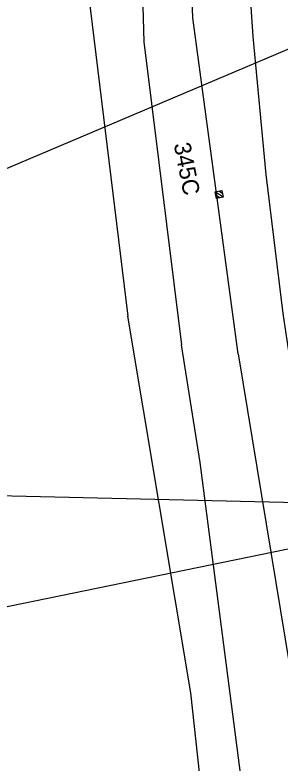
# Model space of a CAD drawing. Extents: x -545846 to -545044, y -1122650 to -1119108.
# Drawn here: x -545674.1 to -545654.2, y -1119663 to -1119607 of the extents above; entities that cross this region are included whole.
import ezdxf

# ---------------------------------------------------------------- set-up
doc = ezdxf.new("R2010")
doc.units = 0
for name, color, linetype in [('Vrstva 1 - Koleje', 7, 'Continuous'), ('Vrstva 11', 7, 'Continuous'), ('Vrstva 49', 7, 'Continuous'), ('Vrstva 62', 7, 'Continuous'), ('Vrstva 63', 7, 'Continuous')]:
    doc.layers.add(name, color=color, linetype=linetype)

msp = doc.modelspace()

# ---------------------------------------------------------------- linework, layer by layer
at = {"layer": 'Vrstva 1 - Koleje'}
msp.add_lwpolyline([(-545673.811, -1119482.836), (-545671.313, -1119495.675), (-545669.505, -1119504.975), (-545667.947, -1119513.018), (-545662.4, -1119541.424), (-545660.697, -1119551.332), (-545659.275, -1119561.505), (-545658.148, -1119572.104), (-545657.527, -1119582.463), (-545657.339, -1119589.06), (-545656.945, -1119598.604), (-545656.274, -1119608.583), (-545655.31, -1119618.93), (-545654.021, -1119629.341), (-545652.534, -1119639.322), (-545651.124, -1119648.586), (-545649.453, -1119659.616), (-545647.771, -1119670.646), (-545646.146, -1119681.578), (-545645.086, -1119692.159), (-545644.623, -1119702.795), (-545644.886, -1119713.798)], dxfattribs=at)
at = {"layer": 'Vrstva 11'}
for p, q in [((-545658.503, -1119620.61), (-545659.088, -1119620.216)), ((-545658.552, -1119620.351), (-545658.83, -1119620.164)), ((-545658.763, -1119620.661), (-545659.037, -1119620.476))]:
    msp.add_line(p, q, dxfattribs=at)
msp.add_lwpolyline([(-545658.992, -1119620.705), (-545659.088, -1119620.215), (-545658.598, -1119620.119), (-545658.502, -1119620.609)], close=True, dxfattribs=at)
msp.add_lwpolyline([(-545658.992, -1119620.705), (-545659.088, -1119620.215), (-545658.598, -1119620.119), (-545658.502, -1119620.609), (-545658.992, -1119620.705)], dxfattribs=at)
at = {"layer": 'Vrstva 49'}
for points in [[(-545657.384, -1119632.351), (-545660.766, -1119607.19), (-545661.141, -1119596.719)], [(-545668.386, -1119597.845), (-545668.464, -1119606.45), (-545665.632, -1119629.539)], [(-545664.775, -1119597.429), (-545664.431, -1119608.978), (-545661.63, -1119631.691)]]:
    msp.add_lwpolyline(points, dxfattribs=at)
at = {"layer": 'Vrstva 62'}
for points in [[(-545656.326, -1119699.999), (-545660.928, -1119657.766), (-545665.632, -1119629.539)], [(-545653.904, -1119689.166), (-545660.218, -1119640.504), (-545661.63, -1119631.691)], [(-545657.384, -1119632.351), (-545652.8, -1119660.112), (-545648.962, -1119686.501), (-545648.197, -1119699.999)]]:
    msp.add_lwpolyline(points, dxfattribs=at)
at = {"layer": 'Vrstva 63'}
for p, q in [((-545594.493, -1119584.444), (-545679.644, -1119620.554)), ((-545623.894, -1119644.185), (-545676.552, -1119642.968)), ((-545640.086, -1119644.226), (-545697.013, -1119655.883))]:
    msp.add_line(p, q, dxfattribs=at)

# ---------------------------------------------------------------- texts
at = {"layer": 'Vrstva 11'}
msp.add_text('345C', height=1.25, rotation=281.0564, dxfattribs=at).set_placement((-545662.206, -1119616.644))

doc.saveas('drawing.dxf')
